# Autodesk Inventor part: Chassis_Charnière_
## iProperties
Created: 2009-01
Part Number: Chassis_Charnière_
Document SubType Name: Modeling
Designer: claivier
Author: claivier
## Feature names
1. Extrusion1
2. Extrusion2
3. Réseau rectangulaire1 [Rectangular Pattern]
4. Perçage1 [Hole]
5. Extrusion3
